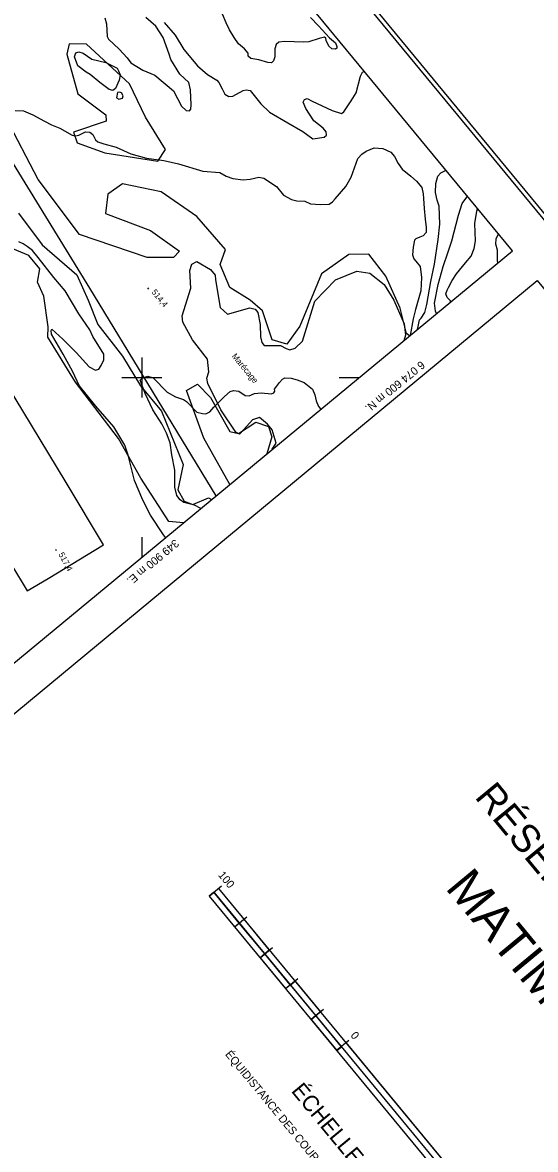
# Model space of a CAD drawing. Extents: x 347312 to 350503, y 6073086 to 6076432.
# Drawn here: x 349840 to 350097, y 6074214 to 6074777 of the extents above; entities that cross this region are included whole.
import ezdxf

# ---------------------------------------------------------------- set-up
doc = ezdxf.new("R2010")
doc.units = 0
for name, color, linetype in [('Level 1', 7, 'Continuous'), ('Level 2', 7, 'Continuous'), ('Level 25', 7, 'Continuous'), ('Level 3', 7, 'Continuous'), ('Level 37', 7, 'Continuous'), ('Level 44', 7, 'Continuous'), ('Level 60', 7, 'Continuous'), ('Level 61', 7, 'Continuous'), ('Level 63', 7, 'Continuous'), ('Level 7', 7, 'Continuous')]:
    doc.layers.add(name, color=color, linetype=linetype)

msp = doc.modelspace()

# ---------------------------------------------------------------- linework, layer by layer
at = {"layer": 'Level 1'}
for points in [[(349981.05, 6074767.59), (349971.26, 6074767.87), (349968.53, 6074767.62), (349967.23, 6074766.48), (349966.59, 6074764.29), (349966.47, 6074760.27), (349965.76, 6074758.3), (349964.84, 6074757.35), (349963.06, 6074757.4), (349958.56, 6074758.7), (349954.45, 6074759.4), (349953.17, 6074760.56), (349953.13, 6074762.15), (349951.41, 6074764.28), (349948.35, 6074766.85), (349946.12, 6074769.88), (349943.86, 6074773.7), (349942.09, 6074777.28), (349940.3, 6074781.64)], [(349984.37, 6074779.97), (349988.32, 6074775.75), (349993.86, 6074769.7), (349996.85, 6074767.35), (349997.52, 6074765.51), (349997.46, 6074764.65), (349996.78, 6074764.19), (349994.93, 6074764.31), (349993.52, 6074765.62), (349992.19, 6074768.37), (349991.99, 6074769.68), (349991.38, 6074770.08), (349988.69, 6074769.47), (349983.57, 6074767.79), (349981.05, 6074767.59)], [(350048.22, 6074646.48), (350050.68, 6074655.53), (350053.22, 6074662.77), (350055.09, 6074668.33), (350058.28, 6074681.18), (350060.25, 6074686.91), (350062.46, 6074690.21), (350062.46, 6074690.21), (350062.63, 6074690.75)], [(350047.29, 6074631.95), (350046.78, 6074633.21), (350046.33, 6074637.26), (350048.22, 6074646.48)]]:
    msp.add_lwpolyline(points, dxfattribs=at)
at = {"layer": 'Level 2'}
for points in [[(349881.53, 6074779.83), (349882.34, 6074776.73), (349882.6, 6074770.44), (349883.36, 6074769.09), (349888.63, 6074764.03), (349892.75, 6074759.72), (349894.42, 6074757.2), (349900.47, 6074753.61), (349906.58, 6074751.11), (349915.78, 6074743.31), (349919.91, 6074735.62), (349922.17, 6074733.53), (349923.92, 6074733.22), (349924.56, 6074734.05), (349924.69, 6074736.3), (349924.39, 6074743.78), (349923.44, 6074747.41), (349919.03, 6074751.62), (349914.56, 6074759.03), (349913.6, 6074761.69), (349910.64, 6074769.86), (349906.94, 6074775.63), (349902.04, 6074779.88)], [(349911.2, 6074777.48), (349916.59, 6074771.13), (349920.97, 6074764.01), (349927.79, 6074755.76), (349932.86, 6074751.37), (349937.45, 6074748.64), (349938.51, 6074747.38), (349940.12, 6074744.37), (349941.48, 6074741.68), (349943.47, 6074740.54)], [(349872.1, 6074752.65), (349867.98, 6074755.71), (349866.34, 6074760.25), (349867.08, 6074762.21), (349868.44, 6074762.82), (349870.64, 6074762.14), (349874.96, 6074759.11), (349882.08, 6074757.37), (349887.72, 6074754.55), (349888.37, 6074753.32), (349889.23, 6074751.23), (349888.74, 6074748.61), (349886.9, 6074744.49), (349885.55, 6074743.44), (349883.69, 6074743.88), (349879.04, 6074747.38), (349874.2, 6074751.38), (349872.1, 6074752.65)], [(349943.47, 6074740.54), (349945.5, 6074740.61), (349950.61, 6074743.48), (349952.25, 6074743.74), (349954.24, 6074743.41), (349959.47, 6074736.8), (349963.88, 6074732.67), (349972.96, 6074727.22), (349980.5, 6074722.91), (349985.51, 6074719.3), (349991.2, 6074720.15), (349992.3, 6074721.06), (349992.17, 6074722.72), (349990.63, 6074724.67), (349985.97, 6074728.29), (349982.04, 6074734.42), (349980.69, 6074737.56), (349981.3, 6074738.88), (349982.6, 6074739.45), (349985.18, 6074738.14), (349995.14, 6074733.43), (349999.8, 6074731.94), (350000.96, 6074732.77), (350004.72, 6074738.25), (350007.24, 6074742.26), (350009.3, 6074750.59), (350010.38, 6074752.6), (350011.14, 6074753.02), (350011.18, 6074753.02)], [(349887.8, 6074742.44), (349887.31, 6074739.82), (349888.58, 6074739.1), (349890.36, 6074739.56), (349890.64, 6074740.82), (349889.85, 6074742.3), (349888.87, 6074742.67), (349887.8, 6074742.44)], [(349836.69, 6074733.48), (349840.76, 6074733.25), (349845.55, 6074731.27), (349851.37, 6074728.06), (349854.77, 6074726.24), (349858.95, 6074724.71), (349865.22, 6074721.15), (349866.8, 6074720.77), (349868.49, 6074721.07), (349871.9, 6074722.88), (349873.98, 6074722.63), (349875.49, 6074721.53), (349876.82, 6074718.79), (349878.03, 6074717.88), (349881, 6074716.82), (349887.16, 6074715.17), (349894.56, 6074711.75), (349902.41, 6074709.59), (349910.96, 6074708.54), (349918.32, 6074706.79), (349930.47, 6074703.21), (349939.04, 6074702.4), (349942.24, 6074700.72), (349945.51, 6074699.47), (349950.7, 6074698.79), (349954.25, 6074699.17), (349958.58, 6074700.13), (349961.05, 6074699.68), (349967.35, 6074695.44), (349970.82, 6074691.2), (349974.81, 6074689), (349977.48, 6074688.29), (349981.59, 6074688.18), (349984.4, 6074686.78), (349989.38, 6074686.44), (349993.6, 6074686.72), (349995.35, 6074687.74), (349996.72, 6074689.32), (350001.96, 6074695.52), (350004.66, 6074700.12), (350007.98, 6074709.43), (350009.93, 6074711.64), (350012.17, 6074713.14), (350016.12, 6074714.74), (350020.57, 6074714.55)], [(350020.57, 6074714.55), (350024.46, 6074712.56), (350026.33, 6074710.42), (350028.11, 6074706.99), (350030.15, 6074704.18), (350034.5, 6074700.58), (350037.35, 6074698.23), (350040.01, 6074695.03), (350040.72, 6074691.74), (350040.86, 6074689.42), (350041.17, 6074684.43), (350041.69, 6074679.2), (350042.2, 6074675.05), (350042.11, 6074672.54), (350040.71, 6074670.9), (350039.08, 6074670.13), (350037.03, 6074669.4), (350036.33, 6074668.65), (350035.67, 6074665.09), (350035.35, 6074661.29), (350036, 6074659.3), (350037, 6074658.15), (350039.13, 6074655.56), (350039.91, 6074650.03), (350039.54, 6074643.35), (350036.92, 6074634), (350035.61, 6074629.32), (350034.1, 6074621.05)], [(350044.56, 6074648.01), (350046.42, 6074656.67), (350048.23, 6074668.94), (350049.09, 6074676.59), (350048.76, 6074685.61), (350047.67, 6074688.71), (350046.78, 6074692.51), (350047.07, 6074696.96), (350047.95, 6074700.57), (350049.5, 6074702.35), (350051.8, 6074703.56), (350051.93, 6074703.71)], [(350053.3, 6074645.02), (350055.17, 6074648.56), (350057.31, 6074651.8), (350061.82, 6074657.39), (350064.74, 6074660.65), (350066.21, 6074664.5), (350066.82, 6074668.41), (350066.46, 6074676.97), (350067.51, 6074683.15), (350067.92, 6074684.36)], [(350077.98, 6074657.31), (350077.85, 6074658.5), (350077.83, 6074663.59), (350076.97, 6074666.72), (350077.22, 6074669.36), (350078.28, 6074671.81)], [(349911.82, 6074520.01), (349910.91, 6074521.49), (349904.26, 6074531.18), (349900.55, 6074538.67), (349896.26, 6074548.57), (349893.25, 6074561.25), (349891.56, 6074566.29), (349885.94, 6074575.37), (349877.04, 6074585.73), (349868.65, 6074596.01), (349865.43, 6074602.81), (349860.67, 6074611.76), (349854.87, 6074621.69), (349854.73, 6074623.58), (349854.95, 6074624.21), (349860.58, 6074619.19), (349867.17, 6074612.45), (349873.6, 6074605.36), (349876.88, 6074603.72), (349878.43, 6074604.28), (349879.64, 6074605.97), (349881.01, 6074608.82), (349880.97, 6074611.68), (349875.51, 6074620.49), (349873.93, 6074623.85), (349868.57, 6074631.91), (349861.68, 6074643.27), (349855.92, 6074649.95), (349848.17, 6074660.07), (349845.3, 6074663.49), (349842.65, 6074665.58), (349840.64, 6074666.79), (349838.48, 6074667.87)], [(350037.86, 6074624.16), (350037.94, 6074624.74), (350038.86, 6074628.93), (350039.63, 6074629.75), (350041.46, 6074632.44), (350042.51, 6074636.47), (350044.56, 6074648.01)], [(350054.41, 6074637.83), (350054.35, 6074638.28), (350052.69, 6074640.03), (350052.09, 6074641.8), (350052.64, 6074643.63), (350053.3, 6074645.02)], [(349929.51, 6074534.62), (349926.31, 6074536.3), (349921.05, 6074537.53), (349919.13, 6074538.97), (349917.51, 6074541.1), (349916.46, 6074545.19), (349916.44, 6074553.71), (349915.08, 6074561.42), (349914.17, 6074567.41), (349912.37, 6074572.14), (349909.95, 6074576.8), (349905.49, 6074583.84), (349901.67, 6074592.01), (349899.16, 6074598.69), (349900.15, 6074599.75), (349903.07, 6074600.71), (349905.67, 6074599.93), (349912.71, 6074592.78), (349916.76, 6074590.35), (349920.8, 6074589.09), (349922.27, 6074588.04), (349927.5, 6074582.7), (349930.39, 6074582.1), (349932.02, 6074581.84), (349933.95, 6074582.92), (349936.04, 6074585.17), (349941.36, 6074590.55), (349944.18, 6074593.05), (349945.8, 6074593.52), (349948.43, 6074593.14), (349951.68, 6074591.12)], [(349951.68, 6074591.12), (349953.75, 6074590.92), (349956.42, 6074592.05), (349959.75, 6074592.42), (349964.82, 6074591.88), (349965.93, 6074592.32), (349966.49, 6074593.22), (349966.41, 6074594.24), (349968.86, 6074597.48), (349970.27, 6074599.27), (349971.46, 6074599.92), (349974.61, 6074599.72), (349977.72, 6074598.94), (349981.15, 6074597.49), (349985.39, 6074594.19), (349986.57, 6074591.44), (349987.16, 6074588.3), (349988.41, 6074585.47), (349989.58, 6074584.26)]]:
    msp.add_lwpolyline(points, dxfattribs=at)
at = {"layer": 'Level 25'}
msp.add_lwpolyline([(349656.2, 6074799.57), (349678.59, 6074762.81), (349696.19, 6074734.05), (349714.33, 6074704.28), (349729.9, 6074678.44), (349746.4, 6074651.32), (349762.26, 6074625.41), (349775.55, 6074603.7), (349792.46, 6074575.9), (349809.32, 6074548.17), (349826.76, 6074519.48), (349842.65, 6074493.39), (349853.14, 6074499.67), (349880.91, 6074516.43), (349862.22, 6074547.58), (349840.44, 6074583.38), (349822.76, 6074612.14), (349806.96, 6074638.27), (349788, 6074669.6), (349768.37, 6074701.83), (349743.34, 6074742.62), (349721.53, 6074778.43)], dxfattribs=at)
at = {"layer": 'Level 3'}
for p, q in [((349902.81, 6074644.85), (349903.32, 6074644.23)), ((349856.86, 6074514.23), (349857.24, 6074513.53))]:
    msp.add_line(p, q, dxfattribs=at)
at = {"layer": 'Level 37'}
msp.add_lwpolyline([(349937.19, 6074540.97), (349874.05, 6074644.62), (349832.75, 6074711.94), (349812.61, 6074745.27), (349809.11, 6074751.23), (349749.75, 6074859.9), (349724.27, 6074900.83), (349698.65, 6074944.47), (349688.46, 6074960.35), (349667.84, 6074994.28), (349654.77, 6075015.26), (349644.24, 6075033.23), (349636.23, 6075046.12), (349615.69, 6075079.37)], dxfattribs=at)
at = {"layer": 'Level 44'}
for points in [[(349920.79, 6074527.41), (349913.51, 6074528.12), (349899.44, 6074549.79), (349888.41, 6074569.62), (349866.85, 6074597.73), (349852.97, 6074620.25), (349853.13, 6074625.38), (349851, 6074640.67), (349847.77, 6074647.7), (349849.04, 6074654.35), (349843.5, 6074660.93), (349831.52, 6074665.97), (349827.88, 6074672.07), (349813.64, 6074696.49), (349806.25, 6074702.43), (349792.21, 6074725.9), (349788.01, 6074734.81), (349776.34, 6074754.38), (349769.21, 6074765.02), (349760.48, 6074781.46)], [(349881.56, 6074712.38), (349908.03, 6074708.19), (349911.81, 6074714), (349901.85, 6074730.18), (349893.87, 6074746.83), (349872.28, 6074766.6), (349863.73, 6074766.84), (349862.43, 6074761.62), (349868.03, 6074741.77), (349881.92, 6074731.23), (349882.12, 6074728.15), (349865.91, 6074722.59), (349867.68, 6074717.27), (349881.56, 6074712.38)], [(350033.88, 6074620.87), (350032.36, 6074621.98), (350029.23, 6074634.61), (350022.08, 6074650.65), (350013.46, 6074661.68), (350003.44, 6074661.57), (349989.9, 6074651.77), (349979, 6074625.67), (349972.5, 6074616.73), (349965.11, 6074618.8), (349960.37, 6074633.35), (349954.1, 6074638.71), (349944.04, 6074645.03), (349939.16, 6074656.55), (349941.81, 6074664.05), (349927.52, 6074680.41), (349909.62, 6074692.89), (349890.26, 6074696.79), (349882.98, 6074691.61), (349881.76, 6074682.04), (349904.42, 6074673.51), (349918.8, 6074663.1), (349915.76, 6074659.97), (349902.66, 6074659.96), (349868.79, 6074671.53), (349848.19, 6074698.93), (349831.95, 6074730.04)], [(349838.38, 6074682.2), (349850.18, 6074666.37), (349867.54, 6074651.37), (349873.15, 6074638.66), (349877.99, 6074626.51), (349890.39, 6074610.68), (349899.33, 6074595.79), (349909.92, 6074583.18), (349920.65, 6074556.6), (349917.98, 6074543.83), (349921.17, 6074538.28), (349925.53, 6074536.63), (349933.42, 6074539.98), (349934.9, 6074539.08)], [(349943.96, 6074546.56), (349931.08, 6074569.68), (349922.37, 6074593.54), (349927.82, 6074596.62), (349934.3, 6074589.97), (349943.99, 6074573.1), (349948.41, 6074572.09), (349957.02, 6074577.78), (349963.41, 6074575.48), (349965.02, 6074570.37), (349962.45, 6074561.84)]]:
    msp.add_lwpolyline(points, dxfattribs=at)
at = {"layer": 'Level 60'}
for p, q in [((349998.63, 6074600), (350008.63, 6074600)), ((349900, 6074520.24), (349900, 6074510.24))]:
    msp.add_line(p, q, dxfattribs=at)
msp.add_lwpolyline([(350502.67, 6074196.28), (348655.35, 6076431.86)], dxfattribs=at)
for points in [[(349159.76, 6073089.49), (347315.28, 6075321.63), (348655.04, 6076428.72), (350499.52, 6074196.58)], [(348779.44, 6073584.28), (350085.28, 6074663.34), (348652.09, 6076397.74), (347346.25, 6075318.68)], [(350097.64, 6074648.45), (350470.23, 6074198.33), (349166.42, 6073119.09), (348793.83, 6073569.21)]]:
    msp.add_lwpolyline(points, close=True, dxfattribs=at)
at = {"layer": 'Level 61'}
for p, q in [((349900, 6074610), (349900, 6074590)), ((349890, 6074600), (349910, 6074600))]:
    msp.add_line(p, q, dxfattribs=at)
at = {"layer": 'Level 63'}
for points in [[(349933.66, 6074340.9), (349939.82, 6074346.01)], [(349935.97, 6074342.82), (350127.03, 6074111.54)], [(349938.29, 6074344.73), (350129.36, 6074113.45)], [(349933.66, 6074340.9), (350124.72, 6074109.61)], [(349946.39, 6074325.49), (349952.58, 6074330.58)], [(349959.13, 6074310.07), (349965.3, 6074315.16)], [(349971.87, 6074294.64), (349978.04, 6074299.74)], [(349984.61, 6074279.22), (349990.77, 6074284.33)], [(349997.34, 6074263.82), (350003.51, 6074268.9)]]:
    msp.add_lwpolyline(points, dxfattribs=at)
for points in [[(349933.66, 6074340.9), (349946.39, 6074325.48), (349948.75, 6074327.4), (349935.99, 6074342.84)], [(349951.02, 6074329.3), (349963.75, 6074313.86), (349961.47, 6074312), (349948.75, 6074327.4)], [(349959.13, 6074310.07), (349971.89, 6074294.63), (349974.21, 6074296.57), (349961.47, 6074312)], [(349976.64, 6074298.4), (349989.3, 6074283.08), (349986.97, 6074281.13), (349974.3, 6074296.47)], [(349984.61, 6074279.22), (349997.45, 6074263.69), (349999.77, 6074265.62), (349986.95, 6074281.16)], [(350002.04, 6074267.65), (350065.75, 6074190.52), (350063.51, 6074188.66), (349999.8, 6074265.77)]]:
    msp.add_lwpolyline(points, close=True, dxfattribs=at)
at = {"layer": 'Level 7'}
msp.add_lwpolyline([(349965.25, 6074564.15), (349967.16, 6074567.17), (349965.15, 6074573.95), (349962.91, 6074576.68), (349958.86, 6074579.97), (349955.28, 6074578.9), (349951.01, 6074574.13), (349948.83, 6074571.71), (349947.07, 6074572.77), (349939.49, 6074583.8), (349933.02, 6074597.1), (349932.47, 6074599.76), (349933.5, 6074602.86), (349932.82, 6074609.12), (349925.26, 6074618.86), (349920.45, 6074627.61), (349920.12, 6074630.91), (349924.46, 6074644.67), (349924.03, 6074653.54), (349925.06, 6074656.63), (349927.54, 6074657.97), (349934.27, 6074653.94), (349936.59, 6074651.12), (349936.78, 6074648.89), (349939.23, 6074635.03), (349942.87, 6074631.68), (349954.02, 6074634.79), (349956.63, 6074634.15), (349957.93, 6074632.56), (349959.13, 6074626.57), (349959.41, 6074620.42), (349959.95, 6074617.6), (349961.17, 6074616.1), (349969.26, 6074616.04), (349972.18, 6074614.48), (349974.05, 6074613.79), (349976.63, 6074614.61), (349980.29, 6074618.25), (349986.56, 6074638.15), (349996.87, 6074648.79), (350007.47, 6074653.2), (350014.08, 6074652.24), (350021.2, 6074646.57), (350025.93, 6074638.76), (350031.23, 6074626.9), (350031.81, 6074621.22), (350030.93, 6074618.43)], dxfattribs=at)

# ---------------------------------------------------------------- texts
at = {"layer": 'Level 3'}
for s, rotation, p in [('514,4', 309.5679, (349904.62, 6074642.61)), ('517,4', 298.4063, (349858.2, 6074511.68))]:
    msp.add_text(s, height=3, rotation=rotation, dxfattribs=at).set_placement(p)
at = {"layer": 'Level 61'}
for s, rotation, p in [('6 074 600 m N.', 219.3644, (350039.52, 6074608.6)), ('349 900 m E. ', 219.813, (349916.52, 6074519.46))]:
    msp.add_text(s, height=4, rotation=rotation, dxfattribs=at).set_placement(p)
at = {"layer": 'Level 63'}
for s, height, rotation, p in [('RÉSERVE INDIENNE DE', 14, 309.6202, (350066.04, 6074390.27)), ('MATIMEKOSH', 18, 309.6202, (350051.35, 6074344.84)), ('100', 4, 309.5597, (349937.92, 6074351.29)), ('0', 4, 309.5597, (350004.12, 6074271.13)), ('ÉQUIDISTANCE DES COURBES DE NIVEAU:  2,0 MÈTRES.', 4, 309.5685, (349941.45, 6074261.7)), ('ÉCHELLE 1:2000', 7.9992, 309.5685, (349974.37, 6074243.38))]:
    msp.add_text(s, height=height, rotation=rotation, dxfattribs=at).set_placement(p)
at = {"layer": 'Level 7'}
msp.add_text('Marécage', height=3, rotation=309.568, dxfattribs=at).set_placement((349944.8, 6074610.55))

doc.saveas('drawing.dxf')
